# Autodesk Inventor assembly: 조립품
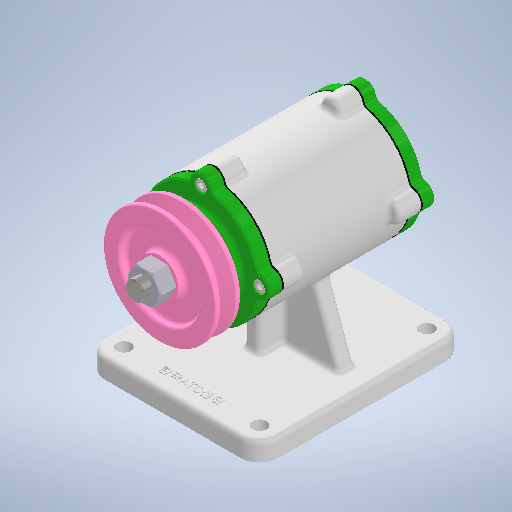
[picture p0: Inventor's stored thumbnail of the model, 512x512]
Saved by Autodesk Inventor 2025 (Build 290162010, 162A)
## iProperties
Created: 2024-08
Part Number: 조립품
Document SubType Name: Assembly
Designer: 학생
Author: 학생
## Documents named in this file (11)
- C:\Users\학생\Desktop\740807V1012\740807V1012\조립품.iam
- C:\Users\학생\Desktop\740807V1012\740807V1012\본체.ipt
- C:\Users\학생\Desktop\740807V1012\740807V1012\V-벨트풀리\V-벨트풀리.ipt
- C:\Users\학생\Desktop\740807V1012\740807V1012\개스킷\개스킷.ipt
- C:\Users\학생\Desktop\740807V1012\740807V1012\너트 M12 x 1.25\너트 M12 x 1.25.ipt
- C:\Users\학생\Desktop\740807V1012\740807V1012\뒤커버\뒤커버.ipt
- C:\Users\학생\Desktop\740807V1012\740807V1012\베어링 6204\베어링 6204.ipt
- C:\Users\학생\Desktop\740807V1012\740807V1012\볼트 M4 x 12\볼트 M4 x 12.ipt
- C:\Users\학생\Desktop\740807V1012\740807V1012\앞커버\앞커버.ipt
- C:\Users\학생\Desktop\740807V1012\740807V1012\축\축.ipt
- C:\Users\학생\Desktop\740807V1012\740807V1012\키 4 x 4\키 4 x 4.ipt
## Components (3 placed, 2 different names)
1. V-벨트풀리:1 — 각도:2
2. 개스킷:1
3. 개스킷:2
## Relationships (1: Angle 1)
- 각도:2 [Angle]: V-벨트풀리:1
